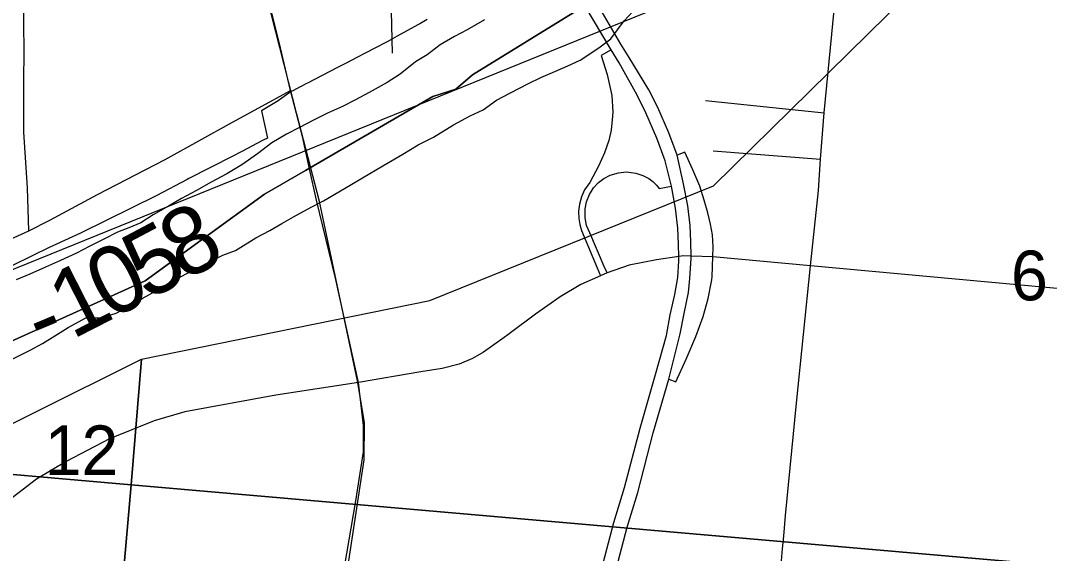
# Model space of a CAD drawing. Extents: x 0 to 34, y 0 to 22.
# Drawn here: x 6.205 to 7.072, y 20.032 to 20.48 of the extents above; entities that cross this region are included whole.
import ezdxf

# ---------------------------------------------------------------- set-up
doc = ezdxf.new("R2010")
doc.units = 0
for name, color, linetype in [('GM_X_City_Street', 7, 'Continuous'), ('GM_X_County_Road', 7, 'Continuous'), ('GM_X_Interchange_Ramps', 7, 'Continuous'), ('GM_X_Interstate_Route', 7, 'Continuous'), ('GM_X_Major_River', 7, 'Continuous'), ('GM_X_Rail_Line', 7, 'Continuous'), ('GM_X_Section', 7, 'Continuous'), ('GM_X_Section_Text', 7, 'Continuous'), ('GM_X_State_Route', 7, 'Continuous'), ('GM_X_Township_Road', 7, 'Continuous'), ('GM_X_Township_Road_Text', 7, 'Continuous')]:
    doc.layers.add(name, color=color, linetype=linetype)

msp = doc.modelspace()

# ---------------------------------------------------------------- linework, layer by layer
at = {"layer": 'GM_X_City_Street'}
for p, q in [((6.78185, 20.4131), (6.88171, 20.40273)), ((6.78818, 20.37087), (6.87881, 20.36366))]:
    msp.add_line(p, q, dxfattribs=at)
for points in [[(6.87036, 20.2738), (6.87691, 20.33746), (6.87881, 20.36366), (6.88171, 20.40273), (6.89136, 20.50093), (6.89768, 20.57589)], [(6.87036, 20.2738), (6.788, 20.28153), (6.76958, 20.28209), (6.76326, 20.28228), (6.7592, 20.2817), (6.74048, 20.27907), (6.71759, 20.27452), (6.69904, 20.26794), (6.6933, 20.26541), (6.67677, 20.25816), (6.65948, 20.24779), (6.63855, 20.23328), (6.61741, 20.21754), (6.61513, 20.21586)], [(6.84771, 20.04639), (6.84932, 20.06375), (6.85842, 20.15843), (6.87036, 20.2738)], [(7.4517, 20.14919), (7.40599, 20.18141), (7.37393, 20.20212), (7.35733, 20.21051), (7.34286, 20.21758), (7.31455, 20.22836), (7.29288, 20.23435), (7.27792, 20.23698), (7.25869, 20.23911), (7.18431, 20.2452), (7.12077, 20.25092), (6.87036, 20.2738)], [(6.61513, 20.21586), (6.61208, 20.21362), (6.59472, 20.20113), (6.58541, 20.19606), (6.57428, 20.19124), (6.55985, 20.18751), (6.54201, 20.18459), (6.48949, 20.17565)], [(6.48949, 20.17565), (6.41974, 20.16506), (6.34311, 20.1509), (6.31729, 20.1434), (6.2798, 20.12841), (6.24316, 20.10925), (6.21817, 20.09426), (6.18652, 20.07011), (6.16153, 20.04595), (6.14238, 20.02679), (6.11405, 19.98764), (6.10156, 19.96349), (6.09323, 19.93434), (6.09013, 19.9103), (6.0916, 19.88736), (6.09531, 19.86589), (6.10271, 19.83776), (6.11603, 19.80667), (6.18784, 19.67065)], [(6.80137, 19.55205), (6.80799, 19.60708), (6.81363, 19.67212), (6.81848, 19.73617), (6.81878, 19.74061), (6.82752, 19.82101), (6.83435, 19.89774), (6.83701, 19.93071), (6.84291, 19.99483), (6.84513, 20.01873), (6.84672, 20.03578), (6.84771, 20.04639)]]:
    msp.add_lwpolyline(points, dxfattribs=at)
at = {"layer": 'GM_X_County_Road'}
for points in [[(6.43714, 20.40215), (6.43212, 20.42149), (6.42272, 20.46217), (6.41314, 20.50077), (6.39771, 20.56437)], [(6.48949, 20.17565), (6.46996, 20.26364), (6.45421, 20.32909), (6.44828, 20.35556), (6.44217, 20.38282), (6.43714, 20.40215)], [(6.56901, 19.75773), (6.53965, 19.80117), (6.52205, 19.82757), (6.51424, 19.83929), (6.50297, 19.86134), (6.49568, 19.8792), (6.48949, 19.89852), (6.48534, 19.92372), (6.47831, 19.95912), (6.47451, 19.98386), (6.47769, 20.02039), (6.48722, 20.07599), (6.49359, 20.11731), (6.49359, 20.13954), (6.48949, 20.17565)]]:
    msp.add_lwpolyline(points, dxfattribs=at)
at = {"layer": 'GM_X_Interchange_Ramps'}
for points in [[(6.70227, 20.45579), (6.69398, 20.4511), (6.69887, 20.43491), (6.70275, 20.41737), (6.70359, 20.40337), (6.70325, 20.39679), (6.70224, 20.38819), (6.70022, 20.37942), (6.69684, 20.36913), (6.69178, 20.35783), (6.68428, 20.3441), (6.67997, 20.33792), (6.67725, 20.33209), (6.6755, 20.32589), (6.67478, 20.32003), (6.67495, 20.31381), (6.67579, 20.30886), (6.67743, 20.30355), (6.69043, 20.27215), (6.6933, 20.26541)], [(6.788, 20.28153), (6.7883, 20.29003), (6.78761, 20.30009), (6.78601, 20.30889), (6.78377, 20.31856), (6.7806, 20.32908), (6.77692, 20.34098), (6.77113, 20.35474), (6.76431, 20.36954), (6.75791, 20.36703)], [(6.69904, 20.26794), (6.69651, 20.2735), (6.68425, 20.30162), (6.68166, 20.30787), (6.68033, 20.31442), (6.68035, 20.3218), (6.68157, 20.32792), (6.68404, 20.33408), (6.68754, 20.33952), (6.69172, 20.34401), (6.69625, 20.34746), (6.70148, 20.35021), (6.70841, 20.35231), (6.71529, 20.35295), (6.72318, 20.352), (6.72899, 20.35005), (6.734, 20.34737), (6.73734, 20.34491), (6.74049, 20.34196), (6.74269, 20.33892), (6.75303, 20.34098)], [(6.75084, 20.17844), (6.75669, 20.17618), (6.76546, 20.19545), (6.7737, 20.21431), (6.77978, 20.23142), (6.784, 20.24643), (6.78701, 20.26218), (6.7875, 20.26502), (6.788, 20.28153)]]:
    msp.add_lwpolyline(points, dxfattribs=at)
at = {"layer": 'GM_X_Interstate_Route'}
for points in [[(6.70227, 20.45579), (6.6805, 20.49257), (6.67275, 20.50567), (6.6257, 20.58002), (6.5854, 20.64582), (6.56484, 20.6802), (6.54411, 20.71392), (6.54081, 20.71981), (6.53259, 20.73448), (6.51894, 20.76129), (6.50726, 20.78794), (6.49904, 20.80785), (6.4895, 20.83515), (6.48209, 20.85769), (6.47453, 20.8822), (6.4714, 20.89388), (6.47008, 20.9)], [(6.7067, 20.01965), (6.71591, 20.05386), (6.72469, 20.08325), (6.73784, 20.13326), (6.75084, 20.17844), (6.76041, 20.2167), (6.76387, 20.2338), (6.76749, 20.25157), (6.76847, 20.26341), (6.76963, 20.28019), (6.76958, 20.28209), (6.7693, 20.29401), (6.7688, 20.30783), (6.76683, 20.32444), (6.76337, 20.34303), (6.75791, 20.36703), (6.75087, 20.3858), (6.7415, 20.40718), (6.73393, 20.42199), (6.71748, 20.44946), (6.71057, 20.46048), (6.6889, 20.49776), (6.68294, 20.50802), (6.65536, 20.5516)], [(6.69546, 20.0236), (6.70467, 20.05781), (6.71345, 20.0872), (6.72661, 20.13721), (6.7396, 20.18239), (6.74896, 20.21537), (6.7521, 20.23264), (6.75602, 20.2499), (6.75838, 20.26418), (6.75929, 20.27814), (6.7592, 20.2817), (6.75896, 20.29196), (6.75846, 20.30577), (6.75649, 20.32239), (6.75303, 20.34098), (6.74786, 20.36241), (6.7408, 20.38139), (6.73139, 20.40273), (6.72417, 20.41748), (6.70918, 20.44477), (6.70227, 20.45579)]]:
    msp.add_lwpolyline(points, dxfattribs=at)
at = {"layer": 'GM_X_Major_River'}
for points in [[(6.19759, 20.19535), (6.21293, 20.20302), (6.2233, 20.20851), (6.23369, 20.21514), (6.24485, 20.22213), (6.25982, 20.23018), (6.27274, 20.2303), (6.28535, 20.23422), (6.29533, 20.23933), (6.30724, 20.24631), (6.32107, 20.25401), (6.3326, 20.26061), (6.34374, 20.26685), (6.35372, 20.27196), (6.36485, 20.27782), (6.37521, 20.28292), (6.38592, 20.28689), (6.40285, 20.29756), (6.41475, 20.30378), (6.42474, 20.30965), (6.43472, 20.31515), (6.4497, 20.3232), (6.46007, 20.32869), (6.48236, 20.34192), (6.49274, 20.34816), (6.51003, 20.35807), (6.52694, 20.36799), (6.53963, 20.37571), (6.55268, 20.38228), (6.5696, 20.39257), (6.58342, 20.40027), (6.59454, 20.40537), (6.60572, 20.4135), (6.61685, 20.41935), (6.63258, 20.42739), (6.64294, 20.4325), (6.65482, 20.43757), (6.66593, 20.44229), (6.67628, 20.44702), (6.69206, 20.45733), (6.70209, 20.46511), (6.7134, 20.48008), (6.72427, 20.49202)], [(6.59565, 20.48098), (6.58105, 20.47254), (6.57031, 20.46706), (6.55839, 20.46008), (6.54721, 20.45157), (6.53759, 20.44568), (6.52447, 20.43531), (6.5137, 20.42831), (6.49834, 20.41988), (6.48682, 20.41366), (6.47607, 20.40818), (6.46342, 20.40235), (6.45153, 20.39652), (6.43963, 20.3903), (6.42888, 20.38482), (6.41658, 20.37747), (6.40424, 20.36822), (6.39114, 20.35899), (6.37846, 20.35127), (6.3654, 20.34431), (6.35311, 20.33734), (6.34044, 20.33076), (6.32929, 20.32415), (6.31661, 20.31681), (6.30622, 20.31018), (6.29588, 20.30583), (6.28631, 20.30223), (6.27442, 20.29601), (6.26252, 20.29017), (6.25178, 20.28469), (6.23836, 20.2785), (6.22571, 20.27268), (6.21268, 20.26687), (6.20119, 20.26216)]]:
    msp.add_lwpolyline(points, dxfattribs=at)
at = {"layer": 'GM_X_Rail_Line'}
msp.add_lwpolyline([(7.01414, 19.09985), (7.01335, 19.10051), (6.97904, 19.12947), (6.93613, 19.17682), (6.90621, 19.22122), (6.8776, 19.29526), (6.65354, 19.63525), (6.50078, 19.8674), (6.48295, 19.92157), (6.47469, 19.98133), (6.49426, 20.11067), (6.49445, 20.14217), (6.48851, 20.17716), (6.4565, 20.32822), (6.43746, 20.40169), (6.34487, 20.76501), (6.3013, 20.9)], dxfattribs=at)
at = {"layer": 'GM_X_Section'}
for points in [[(6.30666, 20.19548), (6.54958, 20.24472), (6.78847, 20.34137), (7.16233, 20.70855), (7.37396, 20.86668), (7.29266, 20.00283), (6.29786, 20.08961)], [(6.02623, 20.49008), (6.76991, 20.50305), (6.02727, 20.20147)], [(6.12431, 20.1046), (6.30666, 20.19548), (6.29786, 20.08961)], [(6.12431, 20.1046), (6.29786, 20.08961), (6.24153, 19.44646)], [(6.29786, 20.08961), (7.29266, 20.00283), (7.19193, 18.99089), (6.64905, 19.04232), (6.24153, 19.44646)]]:
    msp.add_lwpolyline(points, close=True, dxfattribs=at)
at = {"layer": 'GM_X_State_Route'}
msp.add_lwpolyline([(6.54733, 20.48125), (6.54101, 20.47761), (6.53958, 20.47678), (6.522, 20.46724), (6.51803, 20.46502), (6.51724, 20.46458), (6.51248, 20.46191), (6.50388, 20.45746), (6.49574, 20.45325), (6.48795, 20.44922), (6.4801, 20.44515), (6.47164, 20.44077), (6.44644, 20.42773), (6.44506, 20.42702), (6.44313, 20.42602), (6.44052, 20.42467), (6.44032, 20.42457), (6.43457, 20.42159), (6.43272, 20.42058), (6.42277, 20.41355), (6.4225, 20.41339), (6.42041, 20.41211), (6.40772, 20.4045), (6.41268, 20.38154), (6.4098, 20.38003), (6.40803, 20.3791), (6.39162, 20.37049), (6.39002, 20.36967), (6.38362, 20.36638), (6.34657, 20.34732), (6.34504, 20.34654), (6.31964, 20.33302), (6.25531, 20.30144), (6.2284, 20.28919), (6.21561, 20.28288), (6.19615, 20.27329)], dxfattribs=at)
at = {"layer": 'GM_X_Township_Road'}
for p, q in [((6.51803, 20.45309), (6.51689, 20.50431)), ((6.40553, 20.40697), (6.43212, 20.42149))]:
    msp.add_line(p, q, dxfattribs=at)
for points in [[(5.95987, 19.97645), (5.98589, 20.03717), (6.01935, 20.08548), (6.06396, 20.13629), (6.1242, 20.17771), (6.30966, 20.26132), (6.41015, 20.33414), (6.44472, 20.35417), (6.44804, 20.3561), (6.55207, 20.41636), (6.57158, 20.42255), (6.58562, 20.43468), (6.67752, 20.49141), (6.68027, 20.4931), (6.68331, 20.49499), (6.68867, 20.49829), (6.72491, 20.52067), (6.7606, 20.55183), (6.79486, 20.57443), (6.85196, 20.6075), (6.99271, 20.71572), (7.04267, 20.74903), (7.11425, 20.8008)], [(7.11425, 20.8008), (7.04267, 20.74903), (6.99271, 20.71572), (6.85196, 20.6075), (6.79486, 20.57443), (6.7606, 20.55183), (6.72491, 20.52067), (6.68867, 20.49829), (6.68331, 20.49499), (6.68027, 20.4931), (6.67752, 20.49141), (6.58562, 20.43468), (6.57158, 20.42255), (6.55207, 20.41636), (6.44804, 20.3561), (6.44472, 20.35417), (6.41015, 20.33414), (6.30966, 20.26132), (6.1242, 20.17771), (6.06396, 20.13629), (6.01935, 20.08548), (5.98589, 20.03717), (5.95987, 19.97645)], [(6.20786, 20.44697), (6.20771, 20.458), (6.20738, 20.47436), (6.20754, 20.49007), (6.20794, 20.49388)], [(6.21162, 20.30328), (6.21054, 20.33971), (6.20754, 20.38637), (6.20754, 20.4382), (6.20787, 20.44605), (6.20786, 20.44697)], [(6.16227, 20.28924), (6.1642, 20.2892), (6.17537, 20.29018), (6.19007, 20.29371), (6.21162, 20.30328), (6.22948, 20.31234), (6.26947, 20.3339), (6.32651, 20.3635), (6.38336, 20.39487), (6.40553, 20.40697)]]:
    msp.add_lwpolyline(points, dxfattribs=at)

# ---------------------------------------------------------------- texts
at = {"layer": 'GM_X_Section_Text'}
for s, height, p in [('6', 0.04186, (7.0391, 20.24491)), ('12', 0.041856, (6.22493, 20.09772))]:
    msp.add_text(s, height=height, rotation=0.00001, dxfattribs=at).set_placement(p)
at = {"layer": 'GM_X_Township_Road_Text'}
for s, rotation, p in [('8', 27.93387, (6.34209, 20.26058)), ('5', 27.87822, (6.3111, 20.24418)), ('0', 27.68895, (6.27993, 20.22782)), ('1', 27.00715, (6.24809, 20.21159)), ('-', 22.6928, (6.22233, 20.20063))]:
    msp.add_text(s, height=0.05682, rotation=rotation, dxfattribs=at).set_placement(p)

doc.saveas('drawing.dxf')
